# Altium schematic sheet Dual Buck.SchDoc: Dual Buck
size 431 x 279 mm; Date: Not shown in title block; ApprovedBy: Not shown in title block; CheckedBy: Not shown in title block; Author: Not shown in title block; CompanyName: Not shown in title block; DrawnBy: T Zhou; Engineer: Not shown in title block; Organization: Not shown in title block; Address1: Not shown in title block; Address2: Not shown in title block; Address3: Not shown in title block; Address4: Not shown in title block; DocumentNumber: 2; Revision: Use project parameter SCH_Rev; SheetNumber: 2; SheetTotal: 4; PageSetup: Record=PageOptions¦CenterHorizontal=True¦CenterVertical=True¦PrintScale=1.00¦XCorrection=1.00¦YCorrection=1.00¦PrintKind=0¦BorderSize=5000000¦LeftOffset=0¦BottomOffset=0¦Orientation=2¦PaperLength=1000¦PaperWidth=1000¦Scale=100¦PaperSource=15¦PrintQuality=600¦MediaType=1¦DitherType=10¦PaperKind=Letter¦PrintScaleMode=1
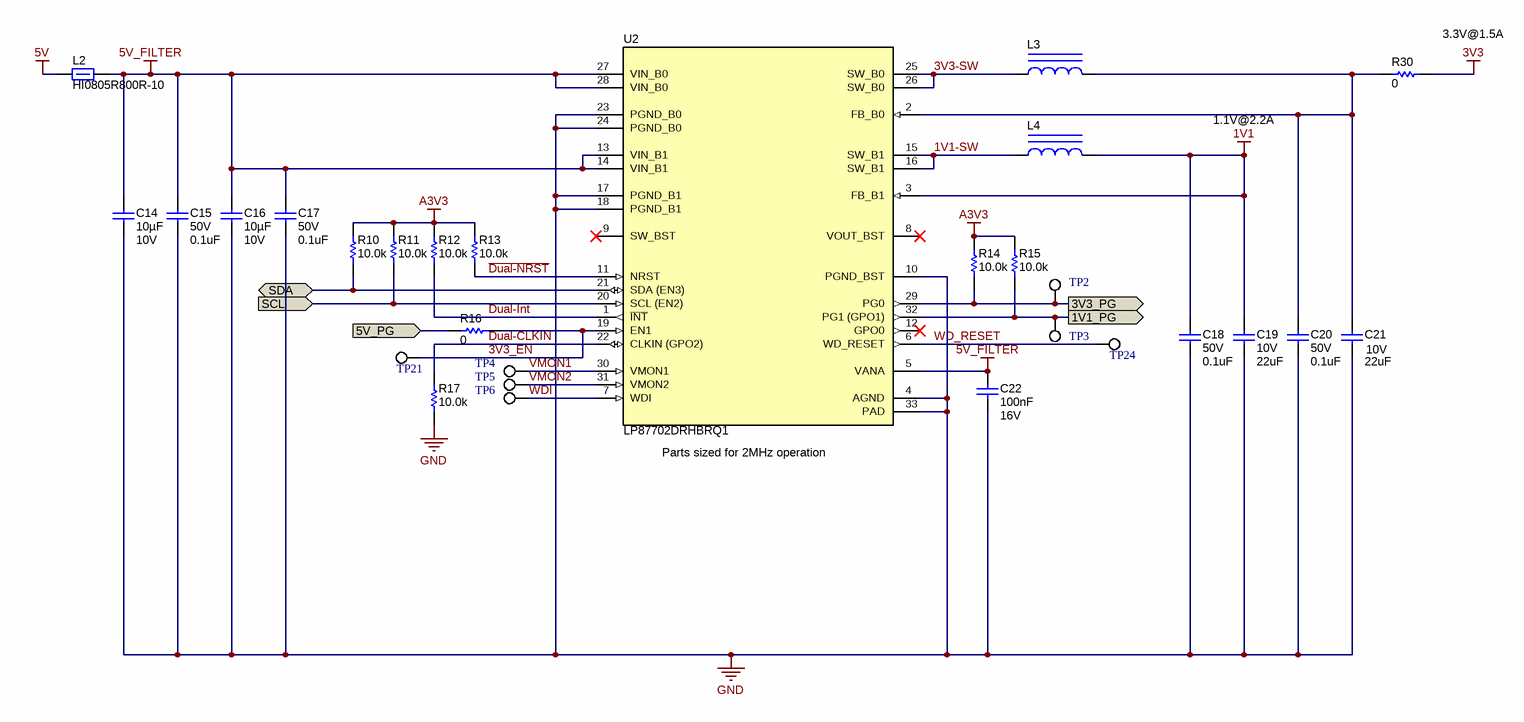
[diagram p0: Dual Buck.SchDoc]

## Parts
C14  Cap_F: 10µF  VDC_V: 10V  [0805_HV]  (hidden comment: C2012X7R1A106K125AC)
C15  VDC_V: 50V  ValueDisplayed: 0.1uF  [0402S]  (hidden comment: CGA2B3X7R1H104K050BB)
C16  Cap_F: 10µF  VDC_V: 10V  [0805_HV]  (hidden comment: C2012X7R1A106K125AC)
C17  VDC_V: 50V  ValueDisplayed: 0.1uF  [0402S]  (hidden comment: CGA2B3X7R1H104K050BB)
C18  VDC_V: 50V  ValueDisplayed: 0.1uF  [0402S]  (hidden comment: CGA2B3X7R1H104K050BB)
C19  VDC_V: 10V  ValueDisplayed: 22uF  [1206_180]  (hidden comment: GCM31CR71A226KE02)
C20  VDC_V: 50V  ValueDisplayed: 0.1uF  [0402S]  (hidden comment: CGA2B3X7R1H104K050BB)
C21  VDC_V: 10V  ValueDisplayed: 22uF  [1206_180]  (hidden comment: GCM31CR71A226KE02)
C22  Cap_F: 100nF  VDC_V: 16V  [0603S]  (hidden comment: 0603YC104K4T4A)
L2  HI0805R800R-10  [0805_HV]
L3  VCTA25201B-R47MS6  [VCTA2520]  (value not drawn)
L4  VCTA25201B-R47MS6  [VCTA2520]  (value not drawn)
R10  ValueDisplayed: 10.0k  [0402S]  (hidden comment: RMCF0402FT10K0)
R11  ValueDisplayed: 10.0k  [0402S]  (hidden comment: RMCF0402FT10K0)
R12  ValueDisplayed: 10.0k  [0402S]  (hidden comment: RMCF0402FT10K0)
R13  ValueDisplayed: 10.0k  [0402S]  (hidden comment: RMCF0402FT10K0)
R14  ValueDisplayed: 10.0k  [0402S]  (hidden comment: RMCF0402FT10K0)
R15  ValueDisplayed: 10.0k  [0402S]  (hidden comment: RMCF0402FT10K0)
R16  ValueDisplayed: 0  [0402S]  (hidden comment: CRCW04020000Z0ED)
R17  ValueDisplayed: 10.0k  [0402S]  (hidden comment: RMCF0402FT10K0)
R30  ValueDisplayed: 0  [0603S]  (hidden comment: CRCW06030000Z0EA)
TP2  5002  [Keystone5002]  (value not drawn)
TP3  5002  [Keystone5002]  (value not drawn)
TP4  5002  [Keystone5002]  (value not drawn)
TP5  5002  [Keystone5002]  (value not drawn)
TP6  5002  [Keystone5002]  (value not drawn)
TP21  5002  [Keystone5002]  (value not drawn)
TP24  5002  [Keystone5002]  (value not drawn)
U2  LP87702DRHBRQ1  [RHB0032N]

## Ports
1V1_PG (out), 3V3_PG (out), 5V_PG (in), SCL (in), SDA (bidir)

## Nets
1V1: C18.1 C19.1 L4.2 U2.3(FB_B1)
3V3: R30.2
5V: L2.1
5V_FILTER: C14.1 C15.1 C16.1 C17.1 C22.1 L2.2 U2.5(VANA) U2.13(VIN_B1) U2.14(VIN_B1) U2.27(VIN_B0) U2.28(VIN_B0)
A3V3: R10.2 R11.2 R12.2 R13.2 R14.2 R15.2
GND: C14.2 C15.2 C16.2 C17.2 C18.2 C19.2 C20.2 C21.2 C22.2 R17.1 U2.4(AGND) U2.10(PGND_BST) U2.17(PGND_B1) U2.18(PGND_B1) U2.23(PGND_B0) U2.24(PGND_B0) U2.33(PAD)
1V1-SW: L4.1 U2.15(SW_B1) U2.16(SW_B1)
1V1_PG: R15.1 TP3.1 U2.32(PG1_(GPO1)) ; port 1V1_PG
3V3-SW: L3.1 U2.25(SW_B0) U2.26(SW_B0)
3V3_EN: R16.2 TP21.1 U2.19(EN1)
3V3_PG: R14.1 TP2.1 U2.29(PG0) ; port 3V3_PG
5V_PG: R16.1 ; port 5V_PG
~{Dual-Int}: R12.1 U2.1(~{INT})
~{Dual-NRST}: R13.1 U2.11(NRST)
Dual-CLKIN: R17.2 U2.22(CLKIN_(GPO2))
SCL: R11.1 U2.20(SCL_(EN2)) ; port SCL
SDA: R10.1 U2.21(SDA_(EN3)) ; port SDA
VMON1: TP4.1 U2.30(VMON1)
VMON2: TP5.1 U2.31(VMON2)
WD_RESET: TP24.1 U2.6(WD_RESET)
WDI: TP6.1 U2.7(WDI)
NetC20_1: C20.1 C21.1 L3.2 R30.1 U2.2(FB_B0)

Not connected (* = marked no-connect by the designer): U2 8(VOUT_BST)* 9(SW_BST)* 12(GPO0)*

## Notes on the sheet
- (near R30) 3.3V@1.5A
- 1.1V@2.2A
- (near U2) Parts sized for 2MHz operation

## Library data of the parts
C14 C16 = CMP-0007863-2: CAP, CERM, 10 uF, 10 V, +/- 10%, X7R, 0805; Manufacturer: TDK; SizeAreaWB_mm2: 6.75; SizeArea_mm2: 2.5; AEC Qualified: N; AEC Category: Q200; Value: 10uF; TaMax_C: 125°C; SizeZ_mm: 1.45; TaMin_C: -55°C; SizeY_mm: 1.25; U/M: EA; SizeX_mm: 2; Cap_Case: 0805; ESR_ohm: 1.063m; IRMS_A: 6.32908A; Value1: 0.001063 ohm
C15 C17 C18 C20 = CMP-0006325-2: CAP, CERM, 0.1 uF, 50 V, +/- 10%, X7R, AEC-Q200 Grade 1, 0402; Manufacturer: TDK; TaMin_C: -55°C; Polarized: N; SizeAreaWB_mm2: 3; Value1: 0.039064 ohm; U/M: EA; Value: 0.1uF; TaMax_C: 125°C; SizeZ_mm: 0.6; SizeX_mm: 1; SizeY_mm: 0.5; Cap_Case: 0402; AEC Qualified: Y; Cap_F: 100nF; AEC Category: Q200; ESR_ohm: 0.039064; IRMS_A: 814.669mA
C19 C21 = CMP-0008811-2: CAP, CERM, 22 uF, 10 V, +/- 10%, X7R, AEC-Q200 Grade 1, 1206; Manufacturer: MuRata; TaMin_C: -55°C; Polarized: N; SizeAreaWB_mm2: 10.92; Value1: Unknown; U/M: EA; Value: 22uF; TaMax_C: 125°C; SizeZ_mm: 1.8; SizeX_mm: 3.2; SizeY_mm: 1.6; Cap_Case: 1206; SizeArea_mm2: 5.12; AEC Qualified: Y; Cap_F: 22µF; AEC Grade: 1; AEC Category: Q200
C22 = CMP-0083626-1: CAP, CERM, 0.1 µF, 16 V,+/- 10%, X7R, AEC-Q200 Grade 1, 0603; Manufacturer: AVX; SizeAreaWB_mm2: 4.68; SizeArea_mm2: 1.28; AEC Qualified: Y; AEC Category: Q200; Value: 0.1uF; TaMax_C: 125°C; SizeZ_mm: 1; Polarized: N; TaMin_C: -55°C; SizeY_mm: 0.8; U/M: EA; SizeX_mm: 1.6; Cap_Case: 0603; ValueDisplayed: 0.1µF
L2 = CMP-0003377-1: Ferrite Bead, 80 ohm @ 100 MHz, 5 A, 0805; Manufacturer: Laird-Signal Integrity Products; ZTyp@100MHz_Ohm: 80; SizeAreaWB_mm2: 6.75; DCR_ohm: 0.01; Value1: 0.01 ohm; Value: 80 ohm; Imax_A: 5A; SizeZ_mm: 1.45; SizeX_mm: 2; SizeY_mm: 1.25; SizeArea_mm2: 2.5
L3 L4 = CMP-0059967-1: Inductor, 470 nH, 4 A, 0.026 ohm, SMD; Manufacturer: Cyntec; SizeZ_mm: 1.2; Irms: 4A @ 40C rise; AEC Qualified: N; Isat: 5.6A @ 30% inductance drop; DCR_ohm: 0.026; Ind_H: 470nH; SizeAreaWB_mm2: 10.5; Value: 470nH; Imax_A: 4A; SizeX_mm: 2.5; SizeY_mm: 2; SizeArea_mm2: 5; AEC Category: Q200
R10-R15 R17 = CMP-0026754-1: RES, 10.0 k, 1%, 0.063 W, AEC-Q200 Grade 0, 0402; Manufacturer: Stackpole Electronics Inc; Power_W: 63mW; TempCo: 100 ppm/C; Value_Code: 10k0; U/M: EA; Value: 10.0k; EIA_Code: E96; Res_ohm: 10k; SizeX_mm: 1; SizeY_mm: 0.5; SizeZ_mm: 0.6; Value2: 0.063W; AEC Qualified: Y; VDC_V: 50V; AEC Grade: 0; AEC Category: Q200
R16 = CMP-0026822-3: RES, 0, 5%, 0.063 W, AEC-Q200 Grade 0, 0402; Manufacturer: Vishay-Dale; Power_W: 63mW; TempCo: 200 ppm/C; Value_Code: 0000; Value: 0; EIA_Code: E24; SizeX_mm: 1; SizeY_mm: 0.5; SizeZ_mm: 0.6; Value2: 0.063W; AEC Qualified: Y; VDC_V: 50V; AEC Category: Q200
R30 = CMP-0025697-4: RES, 0, 5%, 0.1 W, AEC-Q200 Grade 0, 0603; Manufacturer: Vishay-Dale; Power_W: 100mW; TempCo: 200 ppm/C; Value_Code: 0000; Value: 0; EIA_Code: E24; SizeX_mm: 1.6; SizeY_mm: 0.8; SizeZ_mm: 1; Value2: 0.1W; SizeArea_mm2: 1.28; AEC Qualified: Y; VDC_V: 75V; AEC Category: Q200
TP2-TP6 TP21 TP24 = CMP-0055139-1: Test Point, Miniature, White, TH; Manufacturer: Keystone; CNHeader: FALSE; Green_Lifecycle: Active; Green_REACh: Passed; ContactFinish: Silver; CT: TRUE
U2 = CMP-0078631-1: Boost and Dual Buck Regulators With Diagnostic Functions, RHB0032N (VQFN-32); Manufacturer: Texas Instruments; SizeZ_mm: 0.9; SizeX_mm: 5; AEC Category: Q200; AEC Qualified: Y; SizeArea_mm2: 25; CompType: IC; SizeAreaWB_mm2: 49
